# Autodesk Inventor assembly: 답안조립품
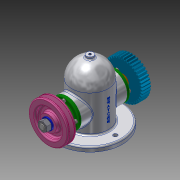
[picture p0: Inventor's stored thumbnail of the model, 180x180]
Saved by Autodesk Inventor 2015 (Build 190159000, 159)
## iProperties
Created: 2019-11
Part Number: 답안조립품
Document SubType Name: Assembly
Designer: LINEART-SSD.D4.16.06
Author: LINEART-SSD.D4.16.06
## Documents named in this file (14)
- C:\Users\LINEART-SSD.D4.16.06\Desktop\491104V1021\답안조립품.iam
- C:\Users\LINEART-SSD.D4.16.06\Desktop\491104V1021\본체.ipt
- C:\Users\LINEART-SSD.D4.16.06\Desktop\491104V1021\491104V1021\축.ipt
- C:\Users\LINEART-SSD.D4.16.06\Desktop\491104V1021\491104V1021\키 5x5x12.ipt
- C:\Users\LINEART-SSD.D4.16.06\Desktop\491104V1021\491104V1021\베어링 6203.ipt
- C:\Users\LINEART-SSD.D4.16.06\Desktop\491104V1021\491104V1021\커버.ipt
- C:\Users\LINEART-SSD.D4.16.06\Desktop\491104V1021\491104V1021\오일 실 26 38 8.ipt
- C:\Users\LINEART-SSD.D4.16.06\Desktop\491104V1021\491104V1021\부시.ipt
- C:\Users\LINEART-SSD.D4.16.06\Desktop\491104V1021\491104V1021\볼트 M4.ipt
- C:\Users\LINEART-SSD.D4.16.06\Desktop\491104V1021\491104V1021\V-벨트풀리.ipt
- V-벨트풀리.ipt
- C:\Users\LINEART-SSD.D4.16.06\Desktop\491104V1021\491104V1021\와셔 12x24.ipt
- C:\Users\LINEART-SSD.D4.16.06\Desktop\491104V1021\491104V1021\너트 M12x1.25.ipt
- C:\Users\LINEART-SSD.D4.16.06\Desktop\491104V1021\491104V1021\스퍼기어.ipt
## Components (1 placed, 1 different names)
1. V-벨트풀리:1
